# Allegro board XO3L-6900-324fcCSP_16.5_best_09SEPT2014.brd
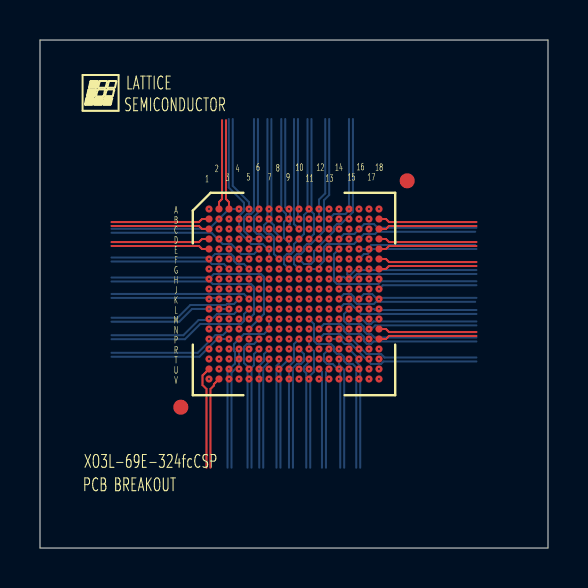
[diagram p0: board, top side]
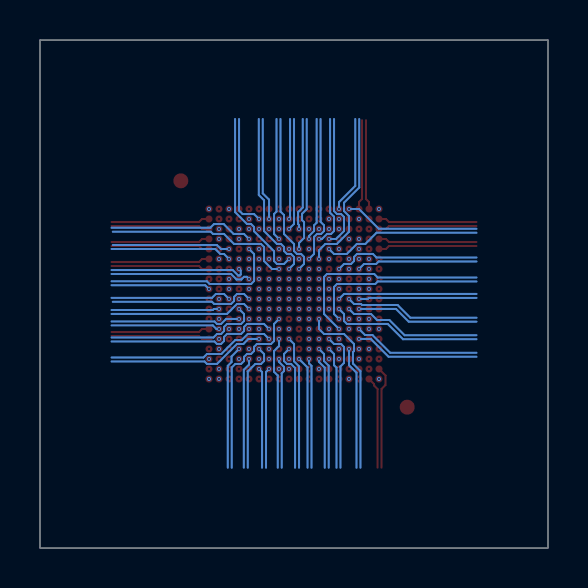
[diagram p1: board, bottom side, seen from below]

Outline 25.4 x 25.4 mm; copper layers: TOP, L2_GND, L3_SIGNAL, L4_SIGNAL, L5_PWR, BOTTOM. Coordinates in mm from the lower left corner of the outline.
Outline path: 0,25.4 25.4,25.4 25.4,0 0,0 0,25.4

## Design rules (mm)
net group CDPB4: nets PB4C PB4D
net group CDPB6: nets PB6C PB6D
net group CDPB7: nets PB7C PB7D
net group CDPB9: nets PB9C PB9D
net group CDPB13: nets PB13C PB13D
net group CDPB15: nets PB15C PB15D
net group CDPB16: nets PB16C PB16D
net group CDPB18: nets PB18C PB18D
net group CDPB21: nets PB21C PB21D
net group CDPB23: nets PB23C PB23D
net group CDPB26: nets PB26C PB26D
net group CDPB31: nets PB31C PB31D
net group CDPB35: nets PB35C PB35D
net group CDPB37: nets PB37C PB37D
net group CDPB38: nets PB38C PB38D
net group CDPL2: nets PL2C PL2D
net group CDPL3: nets PL3C PL3D
net group CDPL4: nets PL4C PL4D
net group CDPL5: nets PL5C PL5D
net group CDPL6: nets PL6C PL6D
net group CDPL7: nets PL7C PL7D
net group CDPL9: nets PL9C PL9D
net group CDPL10: nets PL10C PL10D
net group CDPL15: nets PL15C PL15D
net group CDPL16: nets PL16C PL16D
net group CDPL18: nets PL18C PL18D
net group CDPL19: nets PL19C PL19D
net group CDPL21: nets PL21C PL21D
net group CDPL23: nets PL23C PL23D
net group CDPL24: nets PL24C PL24D
net group CDPL25: nets PL25C PL25D
net group CDPR2: nets PR2C PR2D
net group CDPR3: nets PR3C PR3D
net group CDPR4: nets PR4C PR4D
net group CDPR6: nets PR6C PR6D
net group CDPR7: nets PR7C PR7D
net group CDPR8: nets PR8C PR8D
net group CDPR10: nets PR10C PR10D
net group CDPR11: nets PR11C PR11D
net group CDPR16: nets PR16C PR16D
net group CDPR17: nets PR17C PR17D
net group CDPR19: nets PR19C PR19D
net group CDPR21: nets PR21C PR21D
net group CDPR22: nets PR22C PR22D
net group CDPR23: nets PR23C PR23D
net group CDPR24: nets PR24C PR24D
net group CDPR25: nets PR25C PR25D
net group CDPT9: nets PT9C PT9D
net group CDPT10: nets PT10C PT10D
net group CDPT11: nets PT11C PT11D
net group CDPT14: nets PT14C PT14D
net group CDPT17: nets PT17C PT17D
net group CDPT18: nets PT18C PT18D
net group CDPT21: nets PT21C PT21D
net group CDPT22: nets PT22C PT22D
net group CDPT25: nets PT25C PT25D
net group CDPT26: nets PT26C PT26D
net group CDPT27: nets PT27C PT27D
net group CDPT33: nets PT33C PT33D
net group CDPT34: nets PT34C PT34D
net group CDPT35: nets PT35C PT35D
net group CDPT36: nets PT36C PT36D
net group DP1: nets PB16A PB16B
net group DP2: nets PB7A PB7B
net group DP3: nets PB13A PB13B
net group DP4: nets PB18A PB18B
net group PB4: nets PB4A PB4B
net group PB6: nets PB6A PB6B
net group PB9: nets PB9A PB9B
net group PB10: nets PB10A PB10B
net group PB12: nets PB12A PB12B
net group PB15: nets PB15A PB15B
net group PB21: nets PB21A PB21B
net group PB23: nets PB23A PB23B
net group PB26: nets PB26A PB26B
net group PB28: nets PB28A PB28B
net group PB29: nets PB29A PB29B
net group PB31: nets PB31A PB31B
net group PB32: nets PB32A PB32B
net group PB34: nets PB34A PB34B
net group PB35: nets PB35A PB35B
net group PB37: nets PB37A PB37B
net group PB38: nets PB38A PB38B
net group PL2: nets PL2A PL2B
net group PL3: nets PL3A PL3B
net group PL4: nets PL4A PL4B
net group PL5: nets PL5A PL5B
net group PL6: nets PL6A PL6B
net group PL8: nets PL8A PL8B
net group PL9: nets PL9A PL9B
net group PL10: nets PL10A PL10B
net group PL11: nets PL11A PL11B
net group PL12: nets PL12A PL12B
net group PL15: nets PL15A PL15B
net group PL17: nets PL17A PL17B
net group PL18: nets PL18A PL18B
net group PL19: nets PL19A PL19B
net group PL22: nets PL22A PL22B
net group PL23: nets PL23A PL23B
net group PL24: nets PL24A PL24B
net group PL25: nets PL25A PL25B
net group PR2: nets PR2A PR2B
net group PR3: nets PR3A PR3B
net group PR4: nets PR4A PR4B
net group PR5: nets PR5A PR5B
net group PR7: nets PR7A PR7B
net group PR8: nets PR8A PR8B
net group PR9: nets PR9A PR9B
net group PR11: nets PR11A PR11B
net group PR12: nets PR12A PR12B
net group PR15: nets PR15A PR15B
net group PR16: nets PR16A PR16B
net group PR17: nets PR17A PR17B
net group PR18: nets PR18A PR18B
net group PR21: nets PR21A PR21B
net group PR22: nets PR22A PR22B
net group PR23: nets PR23A PR23B
net group PR24: nets PR24A PR24B
net group PR25: nets PR25A PR25B
net group PT9: nets PT9A PT9B
net group PT10: nets PT10A PT10B
net group PT11: nets PT11A PT11B
net group PT12: nets PT12A PT12B
net group PT13: nets PT13A PT13B
net group PT14: nets PT14A PT14B
net group PT15: nets PT15A PT15B
net group PT16: nets PT16A PT16B
net group PT17: nets PT17A PT17B
net group PT18: nets PT18A PT18B
net group PT21: nets PT21A PT21B
net group PT22: nets PT22A PT22B
net group PT25: nets PT25A PT25B
net group PT26: nets PT26A PT26B
net group PT27: nets PT27A PT27B
net group PT28: nets PT28A PT28B
net group PT32: nets PT32A PT32B
net group PT33: nets PT33A PT33B
net group PT34: nets PT34A PT34B
net group PT35: nets PT35A PT35B
net group PT36: nets PT36A PT36B

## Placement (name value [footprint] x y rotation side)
BGA  -  [BGA324N50P18X18_1000X1000X10-1]  12.7 12.7 270 top
NOREF  -  []  1.85 21.54 0 top

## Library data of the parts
BGA = BGA324N50P18X18_1000X1000X10-1

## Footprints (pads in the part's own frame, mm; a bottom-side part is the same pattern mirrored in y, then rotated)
BGA324N50P18X18_1000X1000X10-1
  round 0.75 smd: (-5.66,5.66) (5.66,-5.66)
  round 0.356 smd: A1(-4.25,-4.25) A2(-4.25,-3.75) A3(-4.25,-3.25) A4(-4.25,-2.75) A5(-4.25,-2.25) A6(-4.25,-1.75) A7(-4.25,-1.25) A8(-4.25,-0.75) A9(-4.25,-0.25) A10(-4.25,0.25) A11(-4.25,0.75) A12(-4.25,1.25) A13(-4.25,1.75) A14(-4.25,2.25) A15(-4.25,2.75) A16(-4.25,3.25) A17(-4.25,3.75) A18(-4.25,4.25) B1(-3.75,-4.25) B2(-3.75,-3.75) B3(-3.75,-3.25) B4(-3.75,-2.75) B5(-3.75,-2.25) B6(-3.75,-1.75) B7(-3.75,-1.25) B8(-3.75,-0.75) B9(-3.75,-0.25) B10(-3.75,0.25) B11(-3.75,0.75) B12(-3.75,1.25) B13(-3.75,1.75) B14(-3.75,2.25) B15(-3.75,2.75) B16(-3.75,3.25) B17(-3.75,3.75) B18(-3.75,4.25) C1(-3.25,-4.25) C2(-3.25,-3.75) C3(-3.25,-3.25) C4(-3.25,-2.75) C5(-3.25,-2.25) C6(-3.25,-1.75) C7(-3.25,-1.25) C8(-3.25,-0.75) C9(-3.25,-0.25) C10(-3.25,0.25) C11(-3.25,0.75) C12(-3.25,1.25) C13(-3.25,1.75) C14(-3.25,2.25) C15(-3.25,2.75) C16(-3.25,3.25) C17(-3.25,3.75) C18(-3.25,4.25) D1(-2.75,-4.25) D2(-2.75,-3.75) D3(-2.75,-3.25) D4(-2.75,-2.75) D5(-2.75,-2.25) D6(-2.75,-1.75) D7(-2.75,-1.25) D8(-2.75,-0.75) D9(-2.75,-0.25) D10(-2.75,0.25) D11(-2.75,0.75) D12(-2.75,1.25) D13(-2.75,1.75) D14(-2.75,2.25) D15(-2.75,2.75) D16(-2.75,3.25) D17(-2.75,3.75) D18(-2.75,4.25) E1(-2.25,-4.25) E2(-2.25,-3.75) E3(-2.25,-3.25) E4(-2.25,-2.75) E5(-2.25,-2.25) E6(-2.25,-1.75) E7(-2.25,-1.25) E8(-2.25,-0.75) E9(-2.25,-0.25) E10(-2.25,0.25) E11(-2.25,0.75) E12(-2.25,1.25) E13(-2.25,1.75) E14(-2.25,2.25) E15(-2.25,2.75) E16(-2.25,3.25) E17(-2.25,3.75) E18(-2.25,4.25) F1(-1.75,-4.25) F2(-1.75,-3.75) F3(-1.75,-3.25) F4(-1.75,-2.75) F5(-1.75,-2.25) F6(-1.75,-1.75) F7(-1.75,-1.25) F8(-1.75,-0.75) F9(-1.75,-0.25) F10(-1.75,0.25) F11(-1.75,0.75) F12(-1.75,1.25) F13(-1.75,1.75) F14(-1.75,2.25) F15(-1.75,2.75) F16(-1.75,3.25) F17(-1.75,3.75) F18(-1.75,4.25) G1(-1.25,-4.25) G2(-1.25,-3.75) G3(-1.25,-3.25) G4(-1.25,-2.75) G5(-1.25,-2.25) G6(-1.25,-1.75) G7(-1.25,-1.25) G8(-1.25,-0.75) G9(-1.25,-0.25) G10(-1.25,0.25) G11(-1.25,0.75) G12(-1.25,1.25) G13(-1.25,1.75) G14(-1.25,2.25) G15(-1.25,2.75) G16(-1.25,3.25) G17(-1.25,3.75) G18(-1.25,4.25) H1(-0.75,-4.25) H2(-0.75,-3.75) H3(-0.75,-3.25) H4(-0.75,-2.75) H5(-0.75,-2.25) H6(-0.75,-1.75) H7(-0.75,-1.25) H8(-0.75,-0.75) H9(-0.75,-0.25) H10(-0.75,0.25) H11(-0.75,0.75) H12(-0.75,1.25) H13(-0.75,1.75) H14(-0.75,2.25) H15(-0.75,2.75) H16(-0.75,3.25) H17(-0.75,3.75) H18(-0.75,4.25) J1(-0.25,-4.25) J2(-0.25,-3.75) J3(-0.25,-3.25) J4(-0.25,-2.75) J5(-0.25,-2.25) J6(-0.25,-1.75) J7(-0.25,-1.25) J8(-0.25,-0.75) J9(-0.25,-0.25) J10(-0.25,0.25) J11(-0.25,0.75) J12(-0.25,1.25) J13(-0.25,1.75) J14(-0.25,2.25) J15(-0.25,2.75) J16(-0.25,3.25) J17(-0.25,3.75) J18(-0.25,4.25) K1(0.25,-4.25) K2(0.25,-3.75) K3(0.25,-3.25) K4(0.25,-2.75) K5(0.25,-2.25) K6(0.25,-1.75) K7(0.25,-1.25) K8(0.25,-0.75) K9(0.25,-0.25) K10(0.25,0.25) K11(0.25,0.75) K12(0.25,1.25) K13(0.25,1.75) K14(0.25,2.25) K15(0.25,2.75) K16(0.25,3.25) K17(0.25,3.75) K18(0.25,4.25) L1(0.75,-4.25) L2(0.75,-3.75) L3(0.75,-3.25) L4(0.75,-2.75) L5(0.75,-2.25) L6(0.75,-1.75) L7(0.75,-1.25) L8(0.75,-0.75) L9(0.75,-0.25) L10(0.75,0.25) L11(0.75,0.75) L12(0.75,1.25) L13(0.75,1.75) L14(0.75,2.25) L15(0.75,2.75) L16(0.75,3.25) L17(0.75,3.75) L18(0.75,4.25) M1(1.25,-4.25) M2(1.25,-3.75) M3(1.25,-3.25) M4(1.25,-2.75) M5(1.25,-2.25) M6(1.25,-1.75) M7(1.25,-1.25) M8(1.25,-0.75) M9(1.25,-0.25) M10(1.25,0.25) M11(1.25,0.75) M12(1.25,1.25) M13(1.25,1.75) M14(1.25,2.25) M15(1.25,2.75) M16(1.25,3.25) M17(1.25,3.75) M18(1.25,4.25) N1(1.75,-4.25) N2(1.75,-3.75) N3(1.75,-3.25) N4(1.75,-2.75) N5(1.75,-2.25) N6(1.75,-1.75) N7(1.75,-1.25) N8(1.75,-0.75) N9(1.75,-0.25) N10(1.75,0.25) N11(1.75,0.75) N12(1.75,1.25) N13(1.75,1.75) N14(1.75,2.25) N15(1.75,2.75) N16(1.75,3.25) N17(1.75,3.75) N18(1.75,4.25) P1(2.25,-4.25) P2(2.25,-3.75) P3(2.25,-3.25) P4(2.25,-2.75) P5(2.25,-2.25) P6(2.25,-1.75) P7(2.25,-1.25) P8(2.25,-0.75) P9(2.25,-0.25) P10(2.25,0.25) P11(2.25,0.75) P12(2.25,1.25) P13(2.25,1.75) P14(2.25,2.25) P15(2.25,2.75) P16(2.25,3.25) P17(2.25,3.75) P18(2.25,4.25) R1(2.75,-4.25) R2(2.75,-3.75) R3(2.75,-3.25) R4(2.75,-2.75) R5(2.75,-2.25) R6(2.75,-1.75) R7(2.75,-1.25) R8(2.75,-0.75) R9(2.75,-0.25) R10(2.75,0.25) R11(2.75,0.75) R12(2.75,1.25) R13(2.75,1.75) R14(2.75,2.25) R15(2.75,2.75) R16(2.75,3.25) R17(2.75,3.75) R18(2.75,4.25) T1(3.25,-4.25) T2(3.25,-3.75) T3(3.25,-3.25) T4(3.25,-2.75) T5(3.25,-2.25) T6(3.25,-1.75) T7(3.25,-1.25) T8(3.25,-0.75) T9(3.25,-0.25) T10(3.25,0.25) T11(3.25,0.75) T12(3.25,1.25) T13(3.25,1.75) T14(3.25,2.25) T15(3.25,2.75) T16(3.25,3.25) T17(3.25,3.75) T18(3.25,4.25) U1(3.75,-4.25) U2(3.75,-3.75) U3(3.75,-3.25) U4(3.75,-2.75) U5(3.75,-2.25) U6(3.75,-1.75) U7(3.75,-1.25) U8(3.75,-0.75) U9(3.75,-0.25) U10(3.75,0.25) U11(3.75,0.75) U12(3.75,1.25) U13(3.75,1.75) U14(3.75,2.25) U15(3.75,2.75) U16(3.75,3.25) U17(3.75,3.75) U18(3.75,4.25) V1(4.25,-4.25) V2(4.25,-3.75) V3(4.25,-3.25) V4(4.25,-2.75) V5(4.25,-2.25) V6(4.25,-1.75) V7(4.25,-1.25) V8(4.25,-0.75) V9(4.25,-0.25) V10(4.25,0.25) V11(4.25,0.75) V12(4.25,1.25) V13(4.25,1.75) V14(4.25,2.25) V15(4.25,2.75) V16(4.25,3.25) V17(4.25,3.75) V18(4.25,4.25)

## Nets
GND: BGA.A1 BGA.A18 BGA.F6 BGA.F13 BGA.J8 BGA.J9 BGA.J10 BGA.J11 BGA.K8 BGA.K9 BGA.K10 BGA.K11 BGA.N6 BGA.N13 BGA.V1 BGA.V18
VCC: BGA.H7 BGA.H12 BGA.J7 BGA.J12 BGA.K7 BGA.K12 BGA.L7 BGA.L12
VCCIO0: BGA.H8 BGA.H9 BGA.H10 BGA.H11
VCCIO1: BGA.H6 BGA.J6 BGA.K6 BGA.L6
VCCIO2: BGA.L8 BGA.L9 BGA.L10 BGA.L11
VCCIO3: BGA.L13 BGA.M13
VCCIO4: BGA.J13 BGA.K13
VCCIO5: BGA.G13 BGA.H13
PB4A: BGA.R15
PB4B: BGA.M11
PB4C: BGA.N11
PB4D: BGA.T15
PB6A: BGA.V17
PB6B: BGA.R14
PB6C: BGA.V16
PB6D: BGA.U16
PB7A: BGA.V14
PB7B: BGA.U14
PB7C: BGA.V15
PB7D: BGA.U15
PB9A: BGA.N10
PB9B: BGA.T13
PB9C: BGA.T14
PB9D: BGA.R13
PB10A: BGA.V13
PB10B: BGA.M10
PB12A: BGA.P13
PB12B: BGA.P12
PB13A: BGA.U13
PB13B: BGA.U12
PB13C: BGA.R12
PB13D: BGA.T12
PB15A: BGA.P11
PB15B: BGA.T11
PB15C: BGA.N9
PB15D: BGA.V12
PB16A: BGA.R11
PB16B: BGA.V11
PB16C: BGA.U11
PB16D: BGA.M9
PB18A: BGA.P10
PB18B: BGA.R10
PB18C: BGA.U10
PB18D: BGA.T10
PB21A: BGA.V10
PB21B: BGA.P9
PB21C: BGA.U9
PB21D: BGA.V9
PB23A: BGA.T9
PB23B: BGA.T8
PB23C: BGA.R9
PB23D: BGA.V8
PB26A: BGA.U8
PB26B: BGA.V7
PB26C: BGA.R8
PB26D: BGA.P8
PB28A: BGA.R7
PB28B: BGA.T7
PB29A: BGA.N8
PB29B: BGA.U7
PB31A: BGA.U6
PB31B: BGA.V6
PB31C: BGA.R6
PB31D: BGA.P6
PB32A: BGA.P7
PB32B: BGA.T6
PB34A: BGA.T5
PB34B: BGA.M8
PB35A: BGA.U5
PB35B: BGA.U4
PB35C: BGA.V5
PB35D: BGA.N7
PB37A: BGA.V4
PB37B: BGA.R5
PB37C: BGA.U3
PB37D: BGA.V3
PB38A: BGA.U2
PB38B: BGA.T4
PB38C: BGA.V2
PB38D: BGA.U1
PL2A: BGA.D16
PL2B: BGA.E15
PL2C: BGA.C17
PL2D: BGA.D17
PL3A: BGA.B18
PL3B: BGA.C18
PL3C: BGA.G12
PL3D: BGA.E17
PL4A: BGA.D18
PL4B: BGA.E18
PL4C: BGA.F15
PL4D: BGA.F14
PL5A: BGA.E16
PL5B: BGA.F16
PL5C: BGA.F17
PL5D: BGA.G14
PL6A: BGA.F18
PL6B: BGA.G18
PL6C: BGA.G15
PL6D: BGA.H14
PL7C: BGA.H17
PL7D: BGA.H15
PL8A: BGA.G16
PL8B: BGA.G17
PL9A: BGA.H16
PL9B: BGA.F12
PL9C: BGA.H18
PL9D: BGA.J15
PL10A: BGA.J14
PL10B: BGA.J16
PL10C: BGA.E14
PL10D: BGA.J18
PL11A: BGA.J17
PL11B: BGA.K18
PL12A: BGA.K17
PL12B: BGA.K15
PL15A: BGA.K16
PL15B: BGA.K14
PL15C: BGA.L17
PL15D: BGA.L14
PL16C: BGA.N12
PL16D: BGA.L15
PL17A: BGA.L18
PL17B: BGA.L16
PL18A: BGA.M16
PL18B: BGA.M18
PL18C: BGA.N14
PL18D: BGA.M17
PL19A: BGA.M15
PL19B: BGA.N17
PL19C: BGA.N16
PL19D: BGA.N15
PL21C: BGA.M14
PL21D: BGA.M12
PL22A: BGA.N18
PL22B: BGA.P18
PL23A: BGA.P15
PL23B: BGA.P16
PL23C: BGA.P17
PL23D: BGA.R17
PL24A: BGA.R16
PL24B: BGA.R18
PL24C: BGA.T17
PL24D: BGA.P14
PL25A: BGA.T18
PL25B: BGA.U17
PL25C: BGA.U18
PL25D: BGA.T16
PR2A: BGA.B1
PR2B: BGA.C1
PR2C: BGA.C3
PR2D: BGA.C2
PR3A: BGA.D1
PR3B: BGA.E1
PR3C: BGA.G7
PR3D: BGA.D3
PR4A: BGA.D2
PR4B: BGA.E4
PR4C: BGA.E3
PR4D: BGA.F3
PR5A: BGA.E2
PR5B: BGA.F5
PR6C: BGA.F4
PR6D: BGA.F2
PR7A: BGA.G6
PR7B: BGA.F1
PR7C: BGA.G5
PR7D: BGA.G3
PR8A: BGA.G4
PR8B: BGA.G2
PR8C: BGA.G1
PR8D: BGA.H4
PR9A: BGA.H5
PR9B: BGA.H2
PR10C: BGA.H3
PR10D: BGA.H1
PR11A: BGA.E5
PR11B: BGA.J5
PR11C: BGA.J4
PR11D: BGA.J1
PR12A: BGA.J3
PR12B: BGA.J2
PR15A: BGA.K1
PR15B: BGA.K2
PR16A: BGA.K3
PR16B: BGA.K5
PR16C: BGA.K4
PR16D: BGA.L3
PR17A: BGA.L1
PR17B: BGA.L2
PR17C: BGA.L5
PR17D: BGA.L4
PR18A: BGA.M1
PR18B: BGA.M6
PR19C: BGA.M3
PR19D: BGA.M4
PR21A: BGA.M2
PR21B: BGA.N1
PR21C: BGA.N2
PR21D: BGA.N4
PR22A: BGA.M5
PR22B: BGA.N5
PR22C: BGA.N3
PR22D: BGA.P3
PR23A: BGA.P2
PR23B: BGA.P1
PR23C: BGA.R1
PR23D: BGA.P4
PR24A: BGA.R2
PR24B: BGA.R3
PR24C: BGA.R4
PR24D: BGA.M7
PR25A: BGA.T1
PR25B: BGA.T2
PR25C: BGA.P5
PR25D: BGA.T3
PT9A: BGA.B16
PT9B: BGA.B17
PT9C: BGA.A17
PT9D: BGA.B15
PT10A: BGA.C16
PT10B: BGA.A15
PT10C: BGA.C14
PT10D: BGA.A16
PT11A: BGA.F11
PT11B: BGA.C15
PT11C: BGA.E13
PT11D: BGA.B14
PT12A: BGA.D13
PT12B: BGA.A14
PT12C: BGA.D15
PT13A: BGA.G11
PT13B: BGA.D14
PT14A: BGA.A13
PT14B: BGA.D12
PT14C: BGA.B13
PT14D: BGA.F10
PT15A: BGA.C13
PT15B: BGA.C12
PT16A: BGA.E12
PT16B: BGA.A12
PT16C: BGA.E11
PT17A: BGA.F9
PT17B: BGA.C11
PT17C: BGA.G10
PT17D: BGA.B12
PT18A: BGA.E10
PT18B: BGA.B11
PT18C: BGA.D11
PT18D: BGA.G9
PT21A: BGA.B10
PT21B: BGA.C10
PT21C: BGA.A11
PT21D: BGA.D10
PT22A: BGA.A10
PT22B: BGA.D9
PT22C: BGA.A9
PT22D: BGA.B9
PT25A: BGA.C9
PT25B: BGA.E9
PT25C: BGA.B8
PT25D: BGA.A8
PT26A: BGA.D8
PT26B: BGA.F8
PT26C: BGA.C8
PT26D: BGA.E8
PT27A: BGA.C7
PT27B: BGA.B3
PT27C: BGA.A7
PT27D: BGA.B7
PT28A: BGA.A6
PT28B: BGA.E7
PT32A: BGA.D7
PT32B: BGA.D6
PT33A: BGA.G8
PT33B: BGA.C6
PT33C: BGA.B5
PT33D: BGA.B6
PT34A: BGA.A4
PT34B: BGA.E6
PT34C: BGA.F7
PT34D: BGA.A5
PT35A: BGA.D4
PT35B: BGA.C5
PT35C: BGA.D5
PT35D: BGA.B2
PT36A: BGA.A3
PT36B: BGA.A2
PT36C: BGA.C4
PT36D: BGA.B4

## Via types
v1: diameter 0.203, hole 0.102, TOP to BOTTOM, 200 vias
v2: diameter 0.203, hole 0.102, TOP to L3_SIGNAL, 108 vias

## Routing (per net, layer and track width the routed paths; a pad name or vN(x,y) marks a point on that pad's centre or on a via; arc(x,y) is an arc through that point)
GND:
  vias: v1(8.45,16.95) v1(8.45,8.45) v1(10.95,14.45) v1(10.95,10.95) v1(11.95,12.95) v1(11.95,12.45) v1(12.45,12.95) v1(12.45,12.45) v1(12.95,12.95) v1(12.95,12.45) v1(13.45,12.95) v1(13.45,12.45) v1(14.45,14.45) v1(14.45,10.95) v1(16.95,16.95) v1(16.95,8.45)
VCC:
  vias: v1(11.45,13.45) v1(11.45,12.95) v1(11.45,12.45) v1(11.45,11.95) v1(13.95,13.45) v1(13.95,12.95) v1(13.95,12.45) v1(13.95,11.95)
VCCIO0:
  vias: v1(11.95,13.45) v1(12.45,13.45) v1(12.95,13.45) v1(13.45,13.45)
VCCIO1:
  vias: v1(10.95,13.45) v1(10.95,12.95) v1(10.95,12.45) v1(10.95,11.95)
VCCIO2:
  vias: v1(11.95,11.95) v1(12.45,11.95) v1(12.95,11.95) v1(13.45,11.95)
VCCIO3:
  vias: v1(14.45,11.95) v1(14.45,11.45)
VCCIO4:
  vias: v1(14.45,12.95) v1(14.45,12.45)
VCCIO5:
  vias: v1(14.45,13.95) v1(14.45,13.45)
PB4A: length 6.2
  BOTTOM w0.102: v1(15.45,9.95) 15.82,9.58 15.82,9.3 16.01,9.11 16.01,4.02
PB4B: length 9.1
  BOTTOM w0.102: v1(13.45,11.45) 13.7,11.2 13.7,10.35 13.85,10.2 14.55,10.2 14.7,10.05 14.7,9.85 14.85,9.7 15.05,9.7 15.2,9.55 15.2,9.35 15.35,9.2 15.63,9.2 15.81,9.03 15.81,4.02
PB4C: length 8.4
  L4_SIGNAL w0.102: 15.4,4.02 15.4,8.96 15.2,9.16 15.2,9.51 15.2,9.52 15.2,9.55 15.05,9.7 14.85,9.7 14.7,9.85 14.7,10.55 14.55,10.7 13.7,10.7 v1(13.45,10.95)
PB4D: length 5.5
  L4_SIGNAL w0.102: v1(15.45,9.45) 15.45,9.19 15.6,9.04 15.6,4.02
PB6A: length 4.6
  L4_SIGNAL w0.102: v1(16.45,8.45) 16.15,8.15 16.15,4.02
PB6B: length 7.3
  L4_SIGNAL w0.102: v1(14.95,9.95) 15.26,10.27 15.48,10.27 15.76,9.99 15.76,9.39 16.14,9.01 16.14,8.45 15.95,8.26 15.95,4.02
PB6C: length 4.5
  L3_SIGNAL w0.102: v2(15.95,8.45) 15.95,8.14 16,8.09 16,4.02
PB6D: length 5
  L3_SIGNAL w0.102: v2(15.95,8.95) 15.95,8.8 16.2,8.56 16.2,8.52 16.2,8.51 16.2,4.02
PB7A: length 4.5
  L3_SIGNAL w0.102: 15,4.02 15,8.2 14.95,8.25 v2(14.95,8.45)
PB7B: length 5
  L3_SIGNAL w0.102: 15.2,4.02 15.2,8.7 v2(14.95,8.95)
PB7C: length 4.5
  L3_SIGNAL w0.102: 15.5,4.02 15.5,8.15 15.45,8.2 v2(15.45,8.45)
PB7D: length 5
  L3_SIGNAL w0.102: v2(15.45,8.95) 15.7,8.7 15.7,4.02
PB9A: length 8.4
  L4_SIGNAL w0.102: v1(12.95,10.95) 13.2,10.7 13.2,10.34 13.43,10.11 13.75,10.11 13.85,10.2 14.08,10.2 14.2,10.08 14.2,9.85 14.35,9.7 14.55,9.7 14.7,9.55 14.7,9.33 14.96,9.07 14.96,4.02
PB9B: length 5.6
  L4_SIGNAL w0.102: 14.76,4.02 14.76,8.99 14.45,9.3 v1(14.45,9.45)
PB9C: length 5.5
  BOTTOM w0.102: 15.21,4.02 15.21,8.91 14.95,9.17 v1(14.95,9.45)
PB9D: length 6.5
  BOTTOM w0.102: 15.01,4.02 15.01,8.83 14.64,9.2 14.35,9.2 14.2,9.35 14.2,9.7 v1(14.45,9.95)
PB10A: length 4.5
  L3_SIGNAL w0.102: v2(14.45,8.45) 14.45,8.19 14.5,8.14 14.5,4.02
PB10B: length 9
  L3_SIGNAL w0.102: 14.7,4.02 14.7,11.08 14.57,11.2 13.2,11.2 12.95,11.45 v2(12.95,11.45)
PB12A: length 7.9
  BOTTOM w0.102: v1(14.45,10.45) 14.98,10.45 15.23,10.2 15.55,10.2 16.55,9.2 17.05,9.2 17.17,9.33 21.82,9.33
PB12B: length 8.5
  BOTTOM w0.102: v1(13.95,10.45) 14.2,10.7 15.01,10.7 15.31,10.4 15.63,10.4 16.33,9.7 17.05,9.7 17.23,9.52 21.82,9.52
PB13A: length 5
  BOTTOM w0.102: v1(14.45,8.95) 14.3,8.8 14.3,4.02
PB13B: length 5
  BOTTOM w0.102: v1(13.95,8.95) 14.1,8.8 14.1,4.02
PB13C: length 6.1
  L4_SIGNAL w0.102: 13.89,4.02 13.89,8.66 13.7,8.85 13.7,9.7 v1(13.95,9.95)
PB13D: length 5.6
  L4_SIGNAL w0.102: 14.08,4.02 14.08,8.74 14.2,8.85 14.2,9.2 v1(13.95,9.45)
PB15A: length 6.6
  BOTTOM w0.102: 13.51,4.02 13.51,8.63 13.7,8.81 13.7,9.35 13.7,9.35 13.7,9.85 13.45,10.1 v1(13.45,10.45)
PB15B: length 5.6
  BOTTOM w0.102: 13.31,4.02 13.31,8.74 13.2,8.85 13.2,9.06 13.45,9.3 v1(13.45,9.45)
PB15C: length 8.5
  L3_SIGNAL w0.102: v2(12.45,10.95) 12.7,10.7 14.07,10.7 14.2,10.58 14.2,4.02
PB15D: length 4.5
  L3_SIGNAL w0.102: v2(13.95,8.45) 13.95,8.14 14,8.09 14,4.02
PB16A: length 6
  L3_SIGNAL w0.102: v2(13.45,9.95) 13.7,9.7 13.7,4.02
PB16B: length 4.5
  L3_SIGNAL w0.102: 13.5,4.02 13.5,8.02 13.45,8.08 v2(13.45,8.45)
PB16C: length 4.9
  L4_SIGNAL w0.102: v1(13.45,8.95) 13.45,4.02
PB16D: length 7.9
  L4_SIGNAL w0.102: v1(12.45,11.45) 12.45,10.6 12.85,10.2 13.05,10.2 13.2,10.05 13.2,9.95 13.2,9.95 13.2,8.84 13.25,8.79 13.25,4.02
PB18A: length 6.6
  BOTTOM w0.102: v1(12.95,10.45) 12.7,10.2 12.7,9.33 12.45,9.08 12.45,4.02
PB18B: length 6.4
  BOTTOM w0.102: 12.65,4.02 12.65,9 12.85,9.2 13.05,9.2 13.2,9.35 13.2,9.7 v1(12.95,9.95)
PB18C: length 5
  L4_SIGNAL w0.102: v1(12.95,8.95) 12.82,8.83 12.82,8.58 12.96,8.44 12.96,4.02
PB18D: length 5.6
  L4_SIGNAL w0.102: 12.76,4.02 12.76,8.36 12.61,8.51 12.61,8.97 12.95,9.3 v1(12.95,9.45)
PB21A: length 4.5
  L3_SIGNAL w0.102: v2(12.95,8.45) 12.95,8.08 13,8.02 13,4.02
PB21B: length 6.9
  L3_SIGNAL w0.102: v2(12.45,10.45) 12.7,10.2 12.7,9.35 12.85,9.2 13.05,9.2 13.2,9.05 13.2,4.02
PB21C: length 5
  L3_SIGNAL w0.102: 12.7,4.02 12.7,8.7 v2(12.45,8.95)
PB21D: length 4.5
  L3_SIGNAL w0.102: v2(12.45,8.45) 12.45,8.13 12.5,8.08 12.5,4.02
PB23A: length 5.6
  BOTTOM w0.102: 12.02,4.02 12.02,9.03 v1(12.45,9.45)
PB23B: length 5.5
  BOTTOM w0.102: v1(11.95,9.45) 11.95,9.23 11.82,9.11 11.82,4.02
PB23C: length 6
  L3_SIGNAL w0.102: 12.2,4.02 12.2,9.7 v2(12.45,9.95)
PB23D: length 4.5
  L3_SIGNAL w0.102: v2(11.95,8.45) 11.95,8.07 12,8.01 12,4.02
PB26A: length 5
  L3_SIGNAL w0.102: v2(11.95,8.95) 11.7,8.7 11.7,4.02
PB26B: length 4.5
  L3_SIGNAL w0.102: 11.5,4.02 11.5,7.95 11.45,8 v2(11.45,8.45)
PB26C: length 6.6
  L4_SIGNAL w0.102: v1(11.95,9.95) 12.1,10.1 12.2,10.1 12.38,9.93 12.38,9.77 12.3,9.7 12.2,9.6 12.2,9.13 12.06,8.99 12.06,4.02
PB26D: length 7
  L4_SIGNAL w0.102: v1(11.95,10.45) 12.1,10.3 12.28,10.3 12.57,10.01 12.57,9.76 12.7,9.64 12.7,9.35 12.26,8.91 12.26,4.02
PB28A: length 6.1
  BOTTOM w0.102: v1(11.45,9.95) 11.2,9.7 11.2,9.35 10.96,9.11 10.96,4.02
PB28B: length 5.6
  BOTTOM w0.102: v1(11.45,9.45) 11.45,9.3 11.16,9.02 11.16,4.02
PB29A: length 7.1
  L4_SIGNAL w0.102: 11.65,4.02 11.65,8.62 11.7,8.68 11.7,10.7 v1(11.95,10.95)
PB29B: length 4.9
  L4_SIGNAL w0.102: v1(11.45,8.95) 11.45,4.02
PB31A: length 5
  L3_SIGNAL w0.102: 11.2,4.02 11.2,8.7 v2(10.95,8.95)
PB31B: length 4.5
  L3_SIGNAL w0.102: 11,4.02 11,7.9 10.95,7.95 v2(10.95,8.45)
PB31C: length 6.1
  BOTTOM w0.102: v1(10.95,9.95) 10.7,9.7 10.7,9.14 10.58,9.02 10.58,4.02
PB31D: length 7
  BOTTOM w0.102: 10.38,4.02 10.38,9.08 10.2,9.25 10.2,10.05 10.35,10.2 10.7,10.2 v1(10.95,10.45)
PB32A: length 6.6
  L4_SIGNAL w0.102: 11.02,4.02 11.02,9.01 11.2,9.19 11.2,10.2 v1(11.45,10.45)
PB32B: length 5.5
  L4_SIGNAL w0.102: 10.82,4.02 10.82,9.09 10.95,9.22 v1(10.95,9.45)
PB34A: length 6.1
  L4_SIGNAL w0.102: v1(10.45,9.45) 10.24,9.45 9.26,8.48 9.26,4.02
PB34B: length 9
  L4_SIGNAL w0.102: 9.06,4.02 9.06,8.56 10.2,9.69 10.2,10.05 10.35,10.2 10.55,10.2 10.7,10.35 10.7,10.55 10.85,10.7 11.2,10.7 v1(11.95,11.45)
PB35A: length 5.1
  L3_SIGNAL w0.102: v2(10.45,8.95) 10.2,8.7 10.2,8.01 10.08,7.89 10.08,4.02
PB35B: length 5.1
  L3_SIGNAL w0.102: v2(9.95,8.95) 9.7,8.7 9.7,8.03 9.88,7.85 9.88,4.02
PB35C: length 4.4
  L3_SIGNAL w0.102: v2(10.45,8.45) 10.45,4.02
PB35D: length 7.5
  L3_SIGNAL w0.102: v2(11.45,10.95) 11.2,10.7 10.85,10.7 10.7,10.55 10.7,8.35 10.65,8.3 10.65,4.02
PB37A: length 4.4
  L4_SIGNAL w0.102: v1(9.95,8.45) 9.95,4.02
PB37B: length 6.6
  L4_SIGNAL w0.102: v1(10.45,9.95) 10.7,9.7 10.7,9.25 10.24,8.8 9.94,8.8 9.7,8.56 9.7,8.35 9.75,8.3 9.75,4.02
PB37C: length 5.2
  L3_SIGNAL w0.102: 8.9,4.02 8.9,8.18 9.2,8.48 9.2,8.7 v2(9.45,8.95)
PB37D: length 4.6
  L3_SIGNAL w0.102: 9.1,4.02 9.1,8.1 v2(9.45,8.45)
PB38A: length 5.5
  L3_SIGNAL w0.102: v2(8.95,8.95) 8.75,8.75 3.59,8.75 3.58,8.76
PB38B: length 6.6
  L3_SIGNAL w0.102: 3.58,8.96 8.61,8.96 8.85,9.2 9.7,9.2 v2(9.95,9.45)
PB38C: length 4.6
  TOP w0.102: BGA.V2 8.7,8.2 8.7,8.12 8.52,7.95 8.52,4.02
PB38D: length 5.2
  TOP w0.102: BGA.U1 8.12,8.62 8.12,8.15 8.33,7.95 8.33,4.02
PL2A: length 6.4
  L3_SIGNAL w0.102: 21.76,15.99 16.89,15.99 16.68,16.2 16.34,16.2 16.2,16.05 16.2,15.85 15.95,15.6 v2(15.95,15.45)
PL2B: length 6.8
  L3_SIGNAL w0.102: 21.76,15.79 16.9,15.79 16.8,15.7 16.33,15.7 16.2,15.57 16.2,15.35 16.05,15.2 15.7,15.2 v2(15.45,14.95)
PL2C: length 5.4
  L4_SIGNAL w0.102: v1(16.45,15.95) 16.6,15.8 21.82,15.8
PL2D: length 5.4
  L4_SIGNAL w0.102: v1(16.45,15.45) 16.6,15.6 21.76,15.6
PL3A: length 4.9
  TOP w0.102: 21.82,16.3 17.45,16.3 17.3,16.45 BGA.B18
PL3B: length 4.9
  TOP w0.102: BGA.C18 17.3,15.95 17.45,16.1 21.82,16.1
PL3C: length 8.7
  L3_SIGNAL w0.102: v2(13.95,13.95) 14.2,14.2 14.2,14.55 14.35,14.7 16.05,14.7 16.2,14.85 16.2,15.05 16.34,15.2 16.76,15.2 16.82,15.26 21.76,15.26
PL3D: length 5.4
  L3_SIGNAL w0.102: v2(16.45,14.95) 16.82,14.95 16.94,15.06 21.76,15.06
PL4A: length 4.9
  TOP w0.102: 21.82,15.3 17.45,15.3 17.3,15.45 BGA.D18
PL4B: length 4.9
  TOP w0.102: BGA.E18 17.3,14.95 17.45,15.1 21.82,15.1
PL4C: length 6.5
  L4_SIGNAL w0.102: 21.82,14.83 16.82,14.83 16.7,14.7 15.7,14.7 v1(15.45,14.45)
PL4D: length 7.4
  L4_SIGNAL w0.102: v1(14.95,14.45) 15.7,15.2 16.05,15.2 16.35,14.9 16.62,14.9 16.74,15.02 21.82,15.02
PL5A: length 5.9
  BOTTOM w0.102: v1(15.95,14.95) 16.36,14.95 16.55,15.15 21.76,15.15
PL5B: length 6.1
  BOTTOM w0.102: 21.82,14.95 16.64,14.95 16.38,14.7 16.2,14.7 v1(15.95,14.45)
PL5C: length 5.4
  L4_SIGNAL w0.102: v1(16.45,14.45) 21.82,14.45
PL5D: length 7
  L4_SIGNAL w0.102: 21.82,14.25 16.6,14.25 16.55,14.2 16.42,14.2 16.42,14.2 15.39,14.2 15.38,14.2 15.2,14.2 v1(14.95,13.95)
PL6A: length 4.9
  TOP w0.102: 21.82,14.3 17.45,14.3 17.3,14.45 BGA.F18
PL6B: length 4.9
  TOP w0.102: BGA.G18 17.3,13.95 17.45,14.1 21.82,14.1
PL6C: length 6.9
  BOTTOM w0.102: v1(15.45,13.95) 15.36,13.86 15.36,13.68 15.41,13.63 15.49,13.63 15.76,13.9 21.82,13.9
PL6D: length 7.1
  BOTTOM w0.102: 21.82,13.7 15.85,13.7 15.57,13.43 15.33,13.43 15.2,13.56 15.06,13.56 v1(14.95,13.45)
PL7C: length 5.5
  L3_SIGNAL w0.102: v2(16.45,13.45) 16.6,13.45 16.9,13.75 21.82,13.75
PL7D: length 6.6
  L3_SIGNAL w0.102: v2(15.45,13.45) 15.7,13.7 16.55,13.7 16.8,13.95 21.82,13.95
PL8A: length 6.5
  L3_SIGNAL w0.102: v2(15.95,13.95) 16.2,14.2 16.2,14.55 16.34,14.7 16.64,14.7 16.83,14.5 21.82,14.5
PL8B: length 5.5
  L3_SIGNAL w0.102: v2(16.45,13.95) 16.8,14.3 21.82,14.3
PL9A: length 6
  L4_SIGNAL w0.102: 21.82,13.75 16.43,13.75 16.14,13.45 v1(15.95,13.45)
PL9B: length 8.5
  L4_SIGNAL w0.102: 21.82,13.95 16.35,13.95 16.1,13.7 14.5,13.7 14.49,13.7 14.35,13.7 13.95,14.1 v1(13.95,14.45)
PL9C: length 4.9
  L3_SIGNAL w0.102: v2(16.95,13.45) 17.26,13.45 17.51,13.2 21.76,13.2
PL9D: length 6.6
  L3_SIGNAL w0.102: v2(15.45,12.95) 15.7,13.2 17.23,13.2 17.43,13 21.82,13
PL10A: length 7.1
  L4_SIGNAL w0.102: 21.82,13.42 16.58,13.42 16.36,13.2 15.82,13.2 15.57,12.95 v1(14.95,12.95)
PL10B: length 6
  L4_SIGNAL w0.102: 21.82,13.22 16.66,13.22 16.39,12.95 v1(15.95,12.95)
PL10C: length 8.9
  BOTTOM w0.102: v1(14.95,14.95) 14.7,14.7 14.7,13.35 14.85,13.2 16.92,13.2 17.06,13.34 21.82,13.34
PL10D: length 4.9
  BOTTOM w0.102: 21.82,13.14 17.14,13.14 v1(16.95,12.95)
PL11A: length 5.5
  L3_SIGNAL w0.102: v2(16.45,12.95) 16.7,12.7 16.89,12.7 16.89,12.7 17.05,12.7 17.1,12.65 21.82,12.65
PL11B: length 4.8
  L3_SIGNAL w0.102: v2(16.95,12.45) 21.76,12.45
PL12A: length 5.5
  L4_SIGNAL w0.102: v1(16.45,12.45) 17.51,12.45 17.7,12.64 21.82,12.64
PL12B: length 6.6
  L4_SIGNAL w0.102: 21.82,12.84 17.61,12.84 17.43,12.65 16.6,12.65 16.55,12.7 15.7,12.7 v1(15.45,12.45)
PL15A: length 6.1
  BOTTOM w0.102: 21.82,12.51 16.8,12.51 16.61,12.7 16.2,12.7 v1(15.95,12.45)
PL15B: length 7.3
  BOTTOM w0.102: v1(14.95,12.45) 15.2,12.7 15.55,12.7 15.7,12.55 15.7,12.45 15.7,12.45 15.7,12.35 15.85,12.2 16.69,12.2 16.8,12.31 21.76,12.31
PL15C: length 5.4
  BOTTOM w0.102: v1(16.45,11.95) 16.71,11.95 16.76,11.9 21.82,11.9
PL15D: length 7.2
  BOTTOM w0.102: v1(14.95,11.95) 15.2,12.2 15.55,12.2 16.05,11.7 21.82,11.7
PL16C: length 8.7
  BOTTOM w0.102: v1(13.95,10.95) 14.2,11.2 14.99,11.2 15,11.2 15.05,11.2 15.2,11.05 15.2,10.94 15.2,10.94 15.2,10.85 15.35,10.7 16.05,10.7 16.2,10.55 16.2,10.35 16.34,10.2 16.55,10.2 16.68,10.33 21.82,10.33
PL16D: length 7.8
  BOTTOM w0.102: v1(15.45,11.95) 15.2,11.7 15.2,11.35 15.35,11.2 16.05,11.2 16.2,11.05 16.2,10.85 16.34,10.7 16.55,10.7 16.73,10.52 21.82,10.52
PL17A: length 4.8
  L3_SIGNAL w0.102: v2(16.95,11.95) 21.76,11.95
PL17B: length 5.9
  L3_SIGNAL w0.102: 21.76,12.15 17.48,12.15 17.43,12.2 16.2,12.2 v2(15.95,11.95)
PL18A: length 6.1
  L3_SIGNAL w0.102: v2(15.95,11.45) 16.2,11.7 17.05,11.7 17.27,11.48 21.82,11.48
PL18B: length 4.9
  L3_SIGNAL w0.102: v2(16.95,11.45) 17.12,11.28 21.76,11.28
PL18C: length 7
  L4_SIGNAL w0.102: v1(14.95,10.95) 15.2,11.2 16.76,11.2 16.89,11.08 21.82,11.08
PL18D: length 5.4
  L4_SIGNAL w0.102: 21.82,11.27 17.01,11.27 16.83,11.45 v1(16.45,11.45)
PL19A: length 6.5
  BOTTOM w0.102: v1(15.45,11.45) 16.1,11.45 16.34,11.2 16.55,11.2 16.68,11.33 21.82,11.33
PL19B: length 5.4
  BOTTOM w0.102: 21.82,11.13 16.76,11.13 16.58,10.95 v1(16.45,10.95)
PL19C: length 7.1
  L4_SIGNAL w0.102: v1(15.95,10.95) 15.82,10.83 15.82,10.58 16.2,10.2 16.2,9.85 16.34,9.7 16.57,9.7 16.76,9.9 21.82,9.9
PL19D: length 7.5
  L4_SIGNAL w0.102: v1(15.45,10.95) 15.6,10.8 15.6,10.52 16,10.12 16,9.77 16.33,9.44 16.58,9.44 16.85,9.7 21.82,9.7
PL21C: length 7
  L4_SIGNAL w0.102: v1(14.95,11.45) 15.2,11.7 16.63,11.7 16.8,11.86 21.82,11.86
PL21D: length 8.4
  L4_SIGNAL w0.102: 21.76,12.06 16.84,12.06 16.7,12.2 14.35,12.2 14.2,12.05 14.2,11.7 v1(13.95,11.45)
PL22A: length 4.9
  TOP w0.102: BGA.N18 17.3,10.95 17.45,10.8 21.82,10.8
PL22B: length 4.9
  TOP w0.102: BGA.P18 17.3,10.45 17.45,10.6 21.82,10.6
PL23A: length 7
  L3_SIGNAL w0.102: v2(15.45,10.45) 15.7,10.7 15.7,11.07 15.82,11.2 16.64,11.2 16.83,11 21.82,11
PL23B: length 6
  L3_SIGNAL w0.102: v2(15.95,10.45) 16.2,10.7 16.7,10.7 16.8,10.81 21.82,10.81
PL23C: length 5.4
  L4_SIGNAL w0.102: v1(16.45,10.45) 16.6,10.3 21.82,10.3
PL23D: length 5.4
  L4_SIGNAL w0.102: 21.82,10.1 16.6,10.1 v1(16.45,9.95)
PL24A: length 6.1
  L3_SIGNAL w0.102: v2(15.95,9.95) 16.2,10.2 17.05,10.2 17.1,10.15 17.45,10.15 17.65,9.95 21.82,9.95
PL24B: length 5
  L3_SIGNAL w0.102: 21.82,9.75 17.57,9.75 17.37,9.95 v2(16.95,9.95)
PL24C: length 5.6
  L3_SIGNAL w0.102: 21.76,9.28 17.48,9.28 17.05,9.7 16.7,9.7 v2(16.45,9.45)
PL24D: length 7.7
  L3_SIGNAL w0.102: v2(14.95,10.45) 15.2,10.2 15.2,9.85 15.35,9.7 16.05,9.7 16.2,9.55 16.2,9.35 16.34,9.2 17.27,9.2 17.39,9.08 21.76,9.08
PL25A: length 5.2
  L4_SIGNAL w0.102: v1(16.95,9.45) 16.95,9.15 17.15,8.95 21.76,8.95
PL25B: length 5.4
  L4_SIGNAL w0.102: v1(16.45,8.95) 16.76,8.95 16.96,8.75 21.76,8.75
PL25C: length 5.1
  L3_SIGNAL w0.102: v2(16.95,8.95) 17.2,8.7 17.2,8.35 17.01,8.16 17.01,4.02
PL25D: length 5.9
  L3_SIGNAL w0.102: 16.81,4.02 16.81,8.09 16.7,8.2 16.7,8.56 16.55,8.7 16.34,8.7 16.2,8.85 16.2,9.06 15.95,9.3 v2(15.95,9.45)
PR2A: length 4.9
  TOP w0.102: BGA.B1 8.1,16.45 7.95,16.3 3.58,16.3
PR2B: length 4.9
  TOP w0.102: BGA.C1 8.1,15.95 7.95,16.1 3.58,16.1
PR2C: length 5.9
  L3_SIGNAL w0.102: v2(9.45,15.95) 9.2,15.7 3.64,15.7
PR2D: length 5.3
  L3_SIGNAL w0.102: 3.64,15.9 8.52,15.9 8.57,15.95 v2(8.95,15.95)
PR3A: length 4.9
  TOP w0.102: BGA.D1 8.1,15.45 7.95,15.3 3.58,15.3
PR3B: length 4.9
  TOP w0.102: 3.58,15.1 7.95,15.1 8.1,14.95 BGA.E1
PR3C: length 9.3
  L4_SIGNAL w0.102: 3.58,16 8.51,16 8.81,15.7 9.55,15.7 9.7,15.55 9.7,15.35 9.84,15.2 10.55,15.2 10.7,15.05 10.7,14.34 11.09,13.95 v1(11.45,13.95)
PR3D: length 6
  L4_SIGNAL w0.102: v1(9.45,15.45) 8.78,15.45 8.43,15.8 3.58,15.8
PR4A: length 5.3
  L3_SIGNAL w0.102: v2(8.95,15.45) 3.64,15.45
PR4B: length 6.4
  L3_SIGNAL w0.102: v2(9.95,14.95) 9.7,15.2 8.66,15.2 8.61,15.25 3.64,15.25
PR4C: length 6
  L4_SIGNAL w0.102: 3.58,15.35 8.16,15.35 8.32,15.18 9.22,15.18 v1(9.45,14.95)
PR4D: length 6.3
  L4_SIGNAL w0.102: 3.58,15.15 8.07,15.15 8.24,14.99 9.06,14.99 9.45,14.6 v1(9.45,14.45)
PR5A: length 5.3
  L3_SIGNAL w0.102: 3.64,14.9 8.65,14.9 8.7,14.95 v2(8.95,14.95)
PR5B: length 6.9
  L3_SIGNAL w0.102: 3.64,14.7 8.48,14.7 8.48,14.7 10.2,14.7 v2(10.45,14.45)
PR6C: length 6.8
  L4_SIGNAL w0.102: 3.58,14.7 9.06,14.7 9.2,14.56 9.2,14.35 9.35,14.2 9.7,14.2 v1(9.95,14.45)
PR6D: length 5.4
  L4_SIGNAL w0.102: 3.58,14.5 8.27,14.5 8.33,14.45 v1(8.95,14.45)
PR7A: length 7.4
  L3_SIGNAL w0.102: 3.64,14.2 10.7,14.2 v2(10.95,13.95)
PR7B: length 4.8
  L3_SIGNAL w0.102: 3.64,14.4 7.96,14.4 8.01,14.45 v2(8.45,14.45)
PR7C: length 7.4
  BOTTOM w0.102: 3.58,14.52 8.58,14.52 8.75,14.7 9.55,14.7 9.7,14.55 9.7,14.35 9.85,14.2 10.2,14.2 v1(10.45,13.95)
PR7D: length 6
  BOTTOM w0.102: 3.58,14.33 8.47,14.33 8.59,14.2 9.2,14.2 v1(9.45,13.95)
PR8A: length 6.8
  L4_SIGNAL w0.102: 3.58,14.15 8.8,14.15 8.85,14.2 9.06,14.2 9.2,14.06 9.2,13.85 9.35,13.7 9.7,13.7 v1(9.95,13.95)
PR8B: length 5.4
  L4_SIGNAL w0.102: 8.95,13.98 v1(8.95,13.95) 3.58,13.95
PR8C: length 4.8
  L3_SIGNAL w0.102: 3.64,13.9 7.9,13.9 7.95,13.95 v2(8.45,13.95)
PR8D: length 6.4
  L3_SIGNAL w0.102: 3.64,13.7 9.7,13.7 v2(9.95,13.45)
PR9A: length 7
  L4_SIGNAL w0.102: v1(10.45,13.45) 9.31,13.45 9.06,13.7 8.85,13.7 8.8,13.65 3.58,13.65
PR9B: length 5.4
  L4_SIGNAL w0.102: v1(8.95,13.45) 3.58,13.45
PR10C: length 5.9
  L3_SIGNAL w0.102: v2(9.45,13.45) 9.2,13.2 8.09,13.2 8.08,13.2 3.64,13.2
PR10D: length 4.8
  L3_SIGNAL w0.102: 3.64,13.4 8,13.4 8.05,13.45 v2(8.45,13.45)
PR11A: length 9.2
  L4_SIGNAL w0.102: v1(10.45,14.95) 10.45,14.3 10.7,14.05 10.7,13.35 10.55,13.2 10.05,13.2 9.55,12.7 9.32,12.7 9.14,12.51 3.58,12.51
PR11B: length 7.4
  L4_SIGNAL w0.102: v1(10.45,12.95) 10.1,12.95 9.7,12.55 9.7,12.35 9.55,12.2 9.26,12.2 9.15,12.32 3.58,12.32
PR11C: length 6.4
  L3_SIGNAL w0.102: v2(9.95,12.95) 9.7,12.7 3.64,12.7
PR11D: length 4.8
  L3_SIGNAL w0.102: 3.64,12.9 8.02,12.9 8.08,12.95 v2(8.45,12.95)
PR12A: length 6
  L4_SIGNAL w0.102: 3.58,13.14 8.79,13.14 8.85,13.2 9.2,13.2 v1(9.45,12.95)
PR12B: length 5.4
  L4_SIGNAL w0.102: 3.58,12.94 8.87,12.94 8.88,12.95 v1(8.95,12.95)
PR15A: length 4.8
  L3_SIGNAL w0.102: v2(8.45,12.45) 8.19,12.45 8.14,12.4 3.64,12.4
PR15B: length 5.4
  L3_SIGNAL w0.102: 3.64,12.2 8.7,12.2 v2(8.95,12.45)
PR16A: length 5.9
  BOTTOM w0.102: 3.58,12.5 8.96,12.5 9.01,12.45 v1(9.45,12.45)
PR16B: length 7
  BOTTOM w0.102: 3.58,12.7 10.2,12.7 v1(10.45,12.45)
PR16C: length 6.8
  BOTTOM w0.102: 3.58,11.51 6.88,11.51 7.52,12.15 9.3,12.15 9.35,12.2 9.7,12.2 v1(9.95,12.45)
PR16D: length 6.1
  BOTTOM w0.102: v1(9.45,11.95) 7.6,11.95 6.96,11.32 3.58,11.32
PR17A: length 4.8
  L3_SIGNAL w0.102: v2(8.45,11.95) 3.64,11.95
PR17B: length 5.4
  L3_SIGNAL w0.102: 3.64,11.75 8.18,11.75 8.23,11.7 8.7,11.7 v2(8.95,11.95)
PR17C: length 7.7
  BOTTOM w0.102: 3.58,10.44 7.25,10.44 8.01,11.2 8.55,11.2 8.55,11.2 10.05,11.2 10.2,11.35 10.2,11.7 v1(10.45,11.95)
PR17D: length 6.9
  BOTTOM w0.102: v1(9.95,11.95) 9.7,11.7 8.85,11.7 8.55,11.4 7.93,11.4 7.17,10.64 3.58,10.64
PR18A: length 4.8
  L3_SIGNAL w0.102: 3.64,11.4 8.26,11.4 8.32,11.45 v2(8.45,11.45)
PR18B: length 7.4
  L3_SIGNAL w0.102: 3.64,11.2 10.7,11.2 v2(10.95,11.45)
PR19C: length 6
  L4_SIGNAL w0.102: 3.58,11.76 9,11.76 9.32,11.45 v1(9.45,11.45)
PR19D: length 6.6
  L4_SIGNAL w0.102: v1(9.95,11.45) 9.7,11.7 9.35,11.7 9.09,11.96 3.58,11.96
PR21A: length 5.4
  L4_SIGNAL w0.102: 3.58,11.34 8.39,11.34 8.5,11.45 v1(8.95,11.45)
PR21B: length 5
  L4_SIGNAL w0.102: v1(8.45,10.95) 8.26,11.14 3.58,11.14
PR21C: length 5.5
  L4_SIGNAL w0.102: 3.58,10.64 8.64,10.64 v1(8.95,10.95)
PR21D: length 6.6
  L4_SIGNAL w0.102: v1(9.95,10.95) 9.7,10.7 8.98,10.7 8.72,10.44 3.58,10.44
PR22A: length 8.9
  BOTTOM w0.102: 3.58,13.33 8.51,13.33 8.64,13.2 10.55,13.2 10.7,13.05 10.7,11.7 v1(10.45,11.45)
PR22B: length 10.7
  BOTTOM w0.102: v1(10.45,10.95) 11.2,11.7 11.2,13.55 11.05,13.7 8.69,13.7 8.51,13.52 3.58,13.52
PR22C: length 6.4
  BOTTOM w0.102: v1(9.45,10.95) 9.15,10.65 8.78,10.65 7.89,9.76 3.58,9.76
PR22D: length 6.2
  BOTTOM w0.102: 3.58,9.56 7.97,9.56 8.86,10.45 v1(9.45,10.45)
PR23A: length 5.4
  L3_SIGNAL w0.102: v2(8.95,10.45) 8.7,10.7 3.64,10.7
PR23B: length 4.8
  L3_SIGNAL w0.102: v2(8.45,10.45) 7.83,10.45 7.77,10.5 3.64,10.5
PR23C: length 4.9
  L3_SIGNAL w0.102: v2(8.45,9.95) 8.01,9.95 7.96,10 3.58,10
PR23D: length 6.5
  L3_SIGNAL w0.102: 3.58,10.2 9.7,10.2 v2(9.95,10.45)
PR24A: length 5.5
  L4_SIGNAL w0.102: v1(8.95,9.95) 8.17,9.95 7.86,9.64 3.58,9.64
PR24B: length 6.1
  L4_SIGNAL w0.102: v1(9.45,9.95) 9.2,10.2 8.85,10.2 8.8,10.15 8.09,10.15 7.78,9.84 3.58,9.84
PR24C: length 6.1
  BOTTOM w0.102: v1(9.95,9.95) 9.95,9.14 9.57,8.76 9.57,4.02
PR24D: length 8.9
  BOTTOM w0.102: v1(11.45,11.45) 11.45,10.95 11.2,10.7 10.2,10.7 9.7,10.2 9.7,9.85 9.75,9.8 9.75,9.22 9.38,8.85 9.38,4.02
PR25A: length 4.9
  L3_SIGNAL w0.102: v2(8.45,9.45) 8.14,9.45 8.08,9.5 3.58,9.5
PR25B: length 5.5
  L3_SIGNAL w0.102: v2(8.95,9.45) 8.7,9.7 3.58,9.7
PR25C: length 7.6
  L4_SIGNAL w0.102: 3.58,9.09 8.42,9.09 8.98,9.65 9.3,9.65 9.35,9.7 9.55,9.7 9.7,9.85 9.7,10.05 10.1,10.45 v1(10.45,10.45)
PR25D: length 6.1
  L4_SIGNAL w0.102: v1(9.45,9.45) 9.07,9.45 8.5,8.89 3.58,8.89
PT9A: length 6
  L3_SIGNAL w0.102: 21.76,16.83 17.19,16.83 17.05,16.7 16.2,16.7 v2(15.95,16.45)
PT9B: length 5.4
  L3_SIGNAL w0.102: 21.76,16.64 17.27,16.64 17.08,16.45 v2(16.45,16.45)
PT9C: length 4.6
  L3_SIGNAL w0.102: 16.21,21.45 16.21,17.44 16.45,17.2 v2(16.45,16.95)
PT9D: length 5.2
  L3_SIGNAL w0.102: 16.01,21.45 16.01,17.36 15.91,17.26 15.91,17.26 15.7,17.05 15.7,16.7 v2(15.45,16.45)
PT10A: length 6
  L3_SIGNAL w0.102: v2(15.95,15.95) 15.7,16.2 15.35,16.2 15.2,16.35 15.2,21.45
PT10B: length 4.5
  L3_SIGNAL w0.102: v2(15.45,16.95) 15.45,17.45 15.4,17.5 15.4,21.45
PT10C: length 5.9
  L4_SIGNAL w0.102: v1(14.95,15.95) 15.7,16.7 15.7,17.33 15.93,17.55 15.93,21.45
PT10D: length 4.6
  L4_SIGNAL w0.102: 16.13,21.45 16.13,17.47 15.95,17.29 v1(15.95,16.95)
PT11A: length 9.4
  L4_SIGNAL w0.102: 21.76,16.4 16.42,16.4 15.72,15.7 15.35,15.7 15.2,15.55 15.2,15.33 15.07,15.2 14.85,15.2 14.7,15.05 14.7,14.85 14.55,14.7 14.51,14.7 14.51,14.7 13.7,14.7 v1(13.45,14.45)
PT11B: length 6.6
  L4_SIGNAL w0.102: 21.76,16.59 16.27,16.59 15.63,15.95 v1(15.45,15.95)
PT11C: length 6.7
  L4_SIGNAL w0.102: v1(14.45,14.95) 14.45,15.45 14.7,15.7 14.7,16.89 14.87,17.06 14.87,21.45
PT11D: length 5.2
  L4_SIGNAL w0.102: 15.07,21.45 15.07,17.08 15.2,16.95 15.2,16.7 v1(14.95,16.45)
PT12A: length 6.1
  L3_SIGNAL w0.102: 14.8,21.45 14.8,17.53 14.7,17.43 14.7,15.7 v2(14.45,15.45)
PT12B: length 4.5
  L3_SIGNAL w0.102: 15,21.45 15,17.38 14.95,17.33 v2(14.95,16.95)
PT12C: length 6.5
  L4_SIGNAL w0.102: 21.76,15.33 16.68,15.33 16.55,15.2 16.34,15.2 16.1,15.45 v1(15.45,15.45)
PT13A: length 9.5
  BOTTOM w0.102: v1(13.45,13.95) 13.8,13.95 14.2,14.35 14.2,15.05 14.35,15.2 15.7,15.2 16.2,15.7 16.75,15.7 16.86,15.81 21.76,15.81
PT13B: length 7.3
  BOTTOM w0.102: 21.82,16.01 16.89,16.01 16.7,16.2 16.22,16.2 15.72,15.7 15.2,15.7 v1(14.95,15.45)
PT14A: length 4.5
  L3_SIGNAL w0.102: v2(14.45,16.95) 14.45,17.57 14.4,17.63 14.4,21.45
PT14B: length 6.1
  L3_SIGNAL w0.102: v2(13.95,15.45) 14.2,15.7 14.2,21.45
PT14C: length 5.7
  BOTTOM w0.102: 15.45,21.45 15.45,16.88 15.27,16.7 14.7,16.7 v1(14.45,16.45)
PT14D: length 8.9
  BOTTOM w0.102: v1(12.95,14.45) 13.2,14.2 13.55,14.2 13.7,14.35 13.7,14.84 14.7,15.84 14.7,16.05 14.85,16.2 15.05,16.2 15.65,16.8 15.65,21.45
PT15A: length 5.7
  L4_SIGNAL w0.102: v1(14.45,15.95) 14.2,16.2 14.2,16.84 14.02,17.01 14.02,21.45
PT15B: length 5.7
  L4_SIGNAL w0.102: v1(13.95,15.95) 13.95,16.1 13.7,16.35 13.7,16.83 13.82,16.95 13.82,21.45
PT16A: length 6.6
  L3_SIGNAL w0.102: v2(13.95,14.95) 13.7,15.2 13.7,21.45
PT16B: length 4.5
  L3_SIGNAL w0.102: 13.9,21.45 13.9,17.5 13.95,17.45 v2(13.95,16.95)
PT16C:
  vias: v1(13.45,14.95)
PT17A: length 7.2
  L4_SIGNAL w0.102: 12.41,21.45 12.41,16.34 12.7,16.05 12.7,16.04 12.7,14.7 v1(12.45,14.45)
PT17B: length 6.1
  L4_SIGNAL w0.102: v1(13.45,15.95) 13.3,15.95 13.05,16.2 12.83,16.2 12.61,16.42 12.61,21.45
PT17C: length 8.6
  BOTTOM w0.102: 14.46,21.45 14.46,17.65 14.2,17.39 14.2,15.85 13.55,15.2 13.35,15.2 13.2,15.05 13.2,14.85 13.05,14.7 12.85,14.7 12.7,14.55 12.7,14.2 v1(12.95,13.95)
PT17D: length 5.1
  BOTTOM w0.102: 14.26,21.45 14.26,17.73 13.95,17.42 v1(13.95,16.45)
PT18A: length 7.4
  L4_SIGNAL w0.102: v1(12.95,14.95) 13.2,15.2 13.57,15.2 13.7,15.33 13.7,16.01 13.7,16.01 13.7,16.05 13.55,16.2 13.35,16.2 13.2,16.35 13.2,16.87 13.07,17 13.07,21.45
PT18B: length 5.1
  L4_SIGNAL w0.102: 13.27,21.45 13.27,17.08 13.45,16.9 v1(13.45,16.45)
PT18C: length 6.2
  BOTTOM w0.102: 13.57,21.45 13.57,16.82 13.7,16.7 13.7,15.7 v1(13.45,15.45)
PT18D: length 8.2
  BOTTOM w0.102: 13.38,21.45 13.38,16.82 13.2,16.65 13.2,15.7 12.7,15.2 12.7,14.85 12.55,14.7 12.35,14.7 12.2,14.56 12.2,14.2 v1(12.45,13.95)
PT21A: length 5
  BOTTOM w0.102: v1(12.95,16.45) 12.9,16.5 12.9,21.45
PT21B: length 5.6
  BOTTOM w0.102: v1(12.95,15.95) 12.7,16.2 12.7,21.45
PT21C: length 4.5
  L3_SIGNAL w0.102: 13.4,21.45 13.4,17.44 13.45,17.39 v2(13.45,16.95)
PT21D: length 6.1
  L3_SIGNAL w0.102: v2(12.95,15.45) 13.2,15.7 13.2,16.92 13.2,21.45
PT22A: length 4.5
  L3_SIGNAL w0.102: v2(12.95,16.95) 12.95,17.39 12.9,17.44 12.9,21.45
PT22B: length 6.1
  L3_SIGNAL w0.102: 12.7,21.45 12.7,15.7 v2(12.45,15.45)
PT22C: length 4.5
  L3_SIGNAL w0.102: v2(12.45,16.95) 12.45,17.45 12.4,17.5 12.4,21.45
PT22D: length 5.1
  L3_SIGNAL w0.102: v2(12.45,16.45) 12.2,16.7 12.2,21.45
PT25A: length 5.6
  BOTTOM w0.102: 12.26,21.45 12.26,17.03 12.5,16.79 12.5,16.2 12.45,16.15 v1(12.45,15.95)
PT25B: length 6.7
  BOTTOM w0.102: 12.06,21.45 12.06,16.94 12.3,16.71 12.3,16.4 12.2,16.3 12.2,15.5 12.45,15.25 v1(12.45,14.95)
PT25C: length 5.1
  L3_SIGNAL w0.102: 11.8,21.45 11.8,17.52 11.7,17.42 11.7,16.7 v2(11.95,16.45)
PT25D: length 4.5
  L3_SIGNAL w0.102: v2(11.95,16.95) 11.95,17.37 11.99,17.41 11.99,21.45
PT26A: length 6.2
  BOTTOM w0.102: v1(11.95,15.45) 11.95,15.6 11.7,15.85 11.7,16.13 11.57,16.26 11.57,21.45
PT26B: length 7.5
  BOTTOM w0.102: 11.37,21.45 11.37,16.31 11.2,16.14 11.2,15.85 11.35,15.7 11.55,15.7 11.7,15.56 11.7,14.7 v1(11.95,14.45)
PT26C: length 5.6
  L4_SIGNAL w0.102: 11.81,21.45 11.81,17.09 11.95,16.95 v1(11.95,15.95)
PT26D: length 6.7
  L4_SIGNAL w0.102: 12.01,21.45 12.01,17.17 12.15,17.03 12.15,16.1 12.2,16.05 12.2,15.2 v1(11.95,14.95)
PT27A: length 7.2
  L4_SIGNAL w0.102: 9.36,21.45 9.36,17.1 10.26,16.2 10.55,16.2 10.7,16.05 10.7,15.85 10.85,15.7 11.2,15.7 v1(11.45,15.95)
PT27B: length 5.1
  L4_SIGNAL w0.102: 9.16,21.45 9.16,16.99 9.45,16.7 v1(9.45,16.45)
PT27C: length 4.5
  L3_SIGNAL w0.102: 11.4,21.45 11.4,17.57 11.45,17.51 v2(11.45,16.95)
PT27D: length 5.1
  L3_SIGNAL w0.102: 11.2,21.45 11.2,16.7 v2(11.45,16.45)
PT28A: length 4.5
  L3_SIGNAL w0.102: v2(10.95,16.95) 10.95,17.45 10.9,17.5 10.9,21.45
PT28B: length 6.9
  L3_SIGNAL w0.102: 10.7,21.45 10.7,16.35 10.85,16.2 11.05,16.2 11.2,16.05 11.2,15.2 v2(11.45,14.95)
PT32A: length 6.6
  BOTTOM w0.102: 10.9,21.45 10.9,16.76 10.7,16.57 10.7,15.85 10.85,15.7 11.05,15.7 11.3,15.45 v1(11.45,15.45)
PT32B: length 6.8
  BOTTOM w0.102: v1(10.95,15.45) 10.6,15.45 10.2,15.85 10.2,16.55 10.35,16.7 10.55,16.7 10.7,16.85 10.7,21.45
PT33A: length 7.7
  L4_SIGNAL w0.102: v1(11.95,13.95) 11.7,14.2 11.7,16.06 11.52,16.24 11.52,21.45
PT33B: length 5.7
  L4_SIGNAL w0.102: v1(10.95,15.95) 11.32,16.33 11.32,21.45
PT33C: length 5.2
  L4_SIGNAL w0.102: v1(10.45,16.45) 10.2,16.7 10.2,17.05 10.39,17.24 10.39,21.45
PT33D: length 5.1
  L4_SIGNAL w0.102: v1(10.95,16.45) 10.7,16.7 10.7,17.14 10.59,17.25 10.59,21.45
PT34A: length 6.8
  BOTTOM w0.102: v1(9.95,16.95) 9.45,16.95 8.46,15.96 3.58,15.96
PT34B: length 7.9
  BOTTOM w0.102: 3.58,15.76 8.58,15.76 9.14,15.2 9.56,15.2 10.06,14.7 10.7,14.7 v1(10.95,14.95)
PT34C: length 8.4
  BOTTOM w0.102: v1(11.45,14.45) 11.45,14.89 11.14,15.2 10.91,15.2 10.91,15.2 10.56,15.2 9.95,15.81 9.95,16.6 10.2,16.85 10.2,17.26 9.44,18.02 9.44,21.45
PT34D: length 4.8
  BOTTOM w0.102: 9.64,21.45 9.64,18.11 10.45,17.29 v1(10.45,16.95)
PT35A: length 6.9
  L4_SIGNAL w0.102: v1(9.95,15.45) 9.95,15.7 9.71,15.94 9.17,15.94 8.76,16.35 3.58,16.35
PT35B: length 7.1
  L4_SIGNAL w0.102: 3.58,16.55 8.84,16.55 9.25,16.14 9.97,16.14 10.16,15.95 v1(10.45,15.95)
PT35C: length 7.2
  L3_SIGNAL w0.102: 3.64,16.2 9.39,16.2 9.39,16.2 9.55,16.2 9.7,16.05 9.7,15.89 9.7,15.89 9.7,15.85 9.85,15.7 9.89,15.7 9.89,15.7 10.2,15.7 v2(10.45,15.45)
PT35D: length 5.3
  L3_SIGNAL w0.102: 3.64,16.4 8.59,16.4 8.64,16.45 v2(8.95,16.45)
PT36A: length 4.5
  TOP w0.102: BGA.A3 9.45,17.3 9.3,17.45 9.3,21.39
PT36B: length 4.5
  TOP w0.102: BGA.A2 8.95,17.3 9.1,17.45 9.1,21.39
PT36C: length 5.7
  L3_SIGNAL w0.102: 10.02,21.45 10.02,17.23 10.2,17.05 10.2,16.2 v2(9.95,15.95)
PT36D: length 5.2
  L3_SIGNAL w0.102: 9.82,21.45 9.82,17.26 9.7,17.14 9.7,16.7 v2(9.95,16.45)

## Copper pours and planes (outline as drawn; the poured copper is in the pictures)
GND on L2_GND: 3.58,21.45 11.64,21.45 11.64,13.14 13.76,13.14 13.76,21.45 21.82,21.45 21.82,4.02 3.58,4.02
VCC on L5_PWR: 11.64,11.76 11.26,11.76 11.26,21.45 14.14,21.45 14.14,11.76 13.76,11.76 13.76,12.26 11.64,12.26
VCCIO0 on L2_GND: 11.76,13.26 11.76,21.45 13.64,21.45 13.64,13.26
VCCIO1 on L5_PWR: 3.58,21.45 3.58,4.02 11.14,4.02 11.14,21.45
VCCIO2 on L5_PWR: 11.26,11.64 11.26,4.02 14.14,4.02 14.14,11.64 13.64,11.64 13.64,12.14 11.76,12.14 11.76,11.64
VCCIO3 on L5_PWR: 14.26,12.14 14.26,4.02 21.82,4.02 21.82,12.14
VCCIO4 on L5_PWR: 14.26,13.14 14.26,12.26 21.82,12.26 21.82,13.14
VCCIO5 on L5_PWR: 14.26,13.26 14.26,21.45 21.82,21.45 21.82,13.26

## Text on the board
User.Comments: ASP | AD | 03/09/14 | 03/99/14 | DWG NO: | XO3L-69E-324FCCSP | REVISION | 1.0 | SHEET | 1 | OF | LATTICE SEMICONDUCTOR CORPORATION | XO3L-69E-324FCCSP PCB BREAKOUT
Ref Des/Silkscreen Top: A | B | C | D | E | F | G | H | J | K | L | M | N | P | R | T | U | V | 1 | 2 | 3 | 4 | 5 | 6 | 7 | 8 | 9 | 10 | 11 | 12 | 13 | 14 | 15 | 16 | 17 | 18 | PCB BREAKOUT | XO3L-69E-324fcCSP | SEMICONDUCTOR | LATTICE
PAGE_OUTLINE: SPECIAL INSTRUCTIONS: | LIKE VIA FILL | SPECIFY ANY SPECIAL INSTRUCTIONS | GND     PLANE  (L2) | POWER   PLANE  (L5) | PRIMARY SIDE   (L1) | SECONDARY SIDE (L6) | SECONDARY SILKSCREEN | SECONDARY SOLDERMASK | PRIMARY SOLDERMASK | PRIMARY SILKSCREEN | SIGNAL         (L4) | SIGNAL         (L3) | DESIGNED BY: | APPROVED BY: | SIGNATURES         DATE | REV | 1 | INITIAL RELEASE | SPACE/NECK DOWN SPACE | ESCAPE VIA DRILL | TRACE WIDTH/NECK DWN | ESCAPE VIA PAD | LAND OPENING | PACKAGE SIZE | LAND PAD | PITCH | DESCRIPTION | 0.1016 | 0.3556 | 0.0889 | 0.50 | 10 X 10 | 0.3048 | 0.2032 | MM | 09/03/2014 | DATE | 19.68 | 14.0 | 12.0 | 8.00 | 4.00 | 3.80 | MILS | APPEOVED | X. XXXXX | 6 LAYER STACKUP | PCB BREAKOUT DETAILS | REVISION
DISPLAY_TOP: FIGURE | SIZE | 4.0 | DRILL CHART: TOP to L3_SIGNAL | ALL UNITS ARE IN MILS | TOLERANCE | +0.03/-0.0 | PLATED | QTY | 108
DEVICE_TYPE_TOP: FIGURE | SIZE | 4.0 | DRILL CHART: TOP to BOTTOM | ALL UNITS ARE IN MILS | TOLERANCE | +0.03/-0.0 | PLATED | QTY | 200
